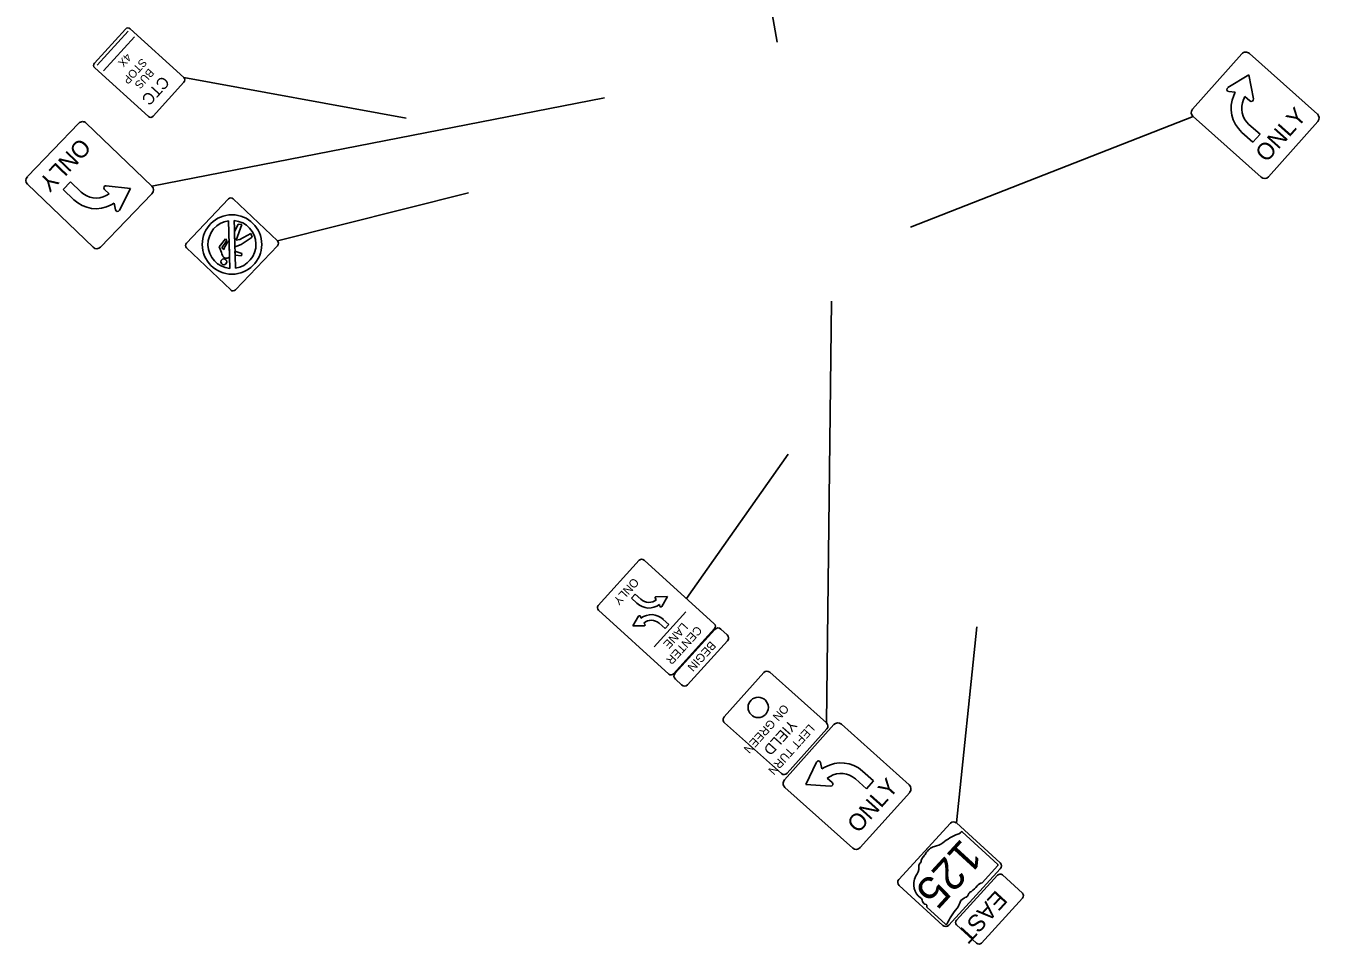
# Model space of a CAD drawing. Extents: x 1472333 to 1475205, y 385587 to 386650.
# Drawn here: x 1472409.3 to 1472790.9, y 386057.3 to 386328.4 of the extents above; entities that cross this region are included whole.
import ezdxf

# ---------------------------------------------------------------- set-up
doc = ezdxf.new("R2010")
doc.units = 0
doc.layers.add('RW_X_CL', color=7, linetype='Continuous')

msp = doc.modelspace()

# ---------------------------------------------------------------- linework, layer by layer
at = {"layer": 'RW_X_CL'}
for p, q in [((1472604.42, 386470.61), (1472631.01, 386323.53)), ((1472430.28, 386316.74), (1472439.42, 386326.82)), ((1472432.13, 386315.06), (1472441.27, 386325.14)), ((1472455.86, 386313.12), (1472521.45, 386301.15)), ((1472764, 386310.12), (1472770.19, 386313.94)), ((1472770.19, 386313.94), (1472771.52, 386306.79)), ((1472446.43, 386281.04), (1472580.06, 386307.15)), ((1472766.18, 386308.74), (1472764.26, 386308.96)), ((1472765.78, 386307.84), (1472766.18, 386308.74)), ((1472769.04, 386307.48), (1472768.64, 386306.57)), ((1472770.49, 386306.21), (1472769.04, 386307.48)), ((1472753.71, 386301.56), (1472670.31, 386268.98)), ((1472771.41, 386294.02), (1472768.14, 386296.93)), ((1472770.22, 386299.26), (1472773.49, 386296.35)), ((1472773.49, 386296.35), (1472771.41, 386294.02)), ((1472422.39, 386282.33), (1472420.22, 386280.08)), ((1472425.54, 386279.3), (1472422.39, 386282.33)), ((1472440.18, 386280.4), (1472432.95, 386281.17)), ((1472420.22, 386280.08), (1472423.38, 386277.04)), ((1472432.45, 386280.1), (1472433.83, 386278.75)), ((1472433.83, 386278.75), (1472432.96, 386278.28)), ((1472436.85, 386273.93), (1472440.18, 386280.4)), ((1472483.5, 386264.88), (1472539.84, 386279.08)), ((1472434.44, 386275.53), (1472435.31, 386276)), ((1472435.31, 386276), (1472435.68, 386274.1)), ((1472469.41, 386256.78), (1472469.08, 386270.86)), ((1472471.87, 386269.86), (1472470.83, 386267.61)), ((1472471.87, 386269.86), (1472470.83, 386267.61)), ((1472471.29, 386265.11), (1472472.98, 386269.73)), ((1472471.29, 386265.11), (1472472.98, 386269.73)), ((1472472.98, 386269.73), (1472471.87, 386269.86)), ((1472472.98, 386269.73), (1472471.87, 386269.86)), ((1472468.18, 386265.46), (1472466.28, 386263.14)), ((1472468.18, 386265.46), (1472466.28, 386263.14)), ((1472468.61, 386264.98), (1472468.18, 386265.46)), ((1472468.61, 386264.98), (1472468.18, 386265.46)), ((1472470.83, 386267.61), (1472470.94, 386263.24)), ((1472472.43, 386265.27), (1472471.29, 386265.11)), ((1472472.43, 386265.27), (1472471.29, 386265.11)), ((1472475.62, 386267.1), (1472472.43, 386265.27)), ((1472475.62, 386267.1), (1472472.43, 386265.27)), ((1472472.81, 386263.86), (1472476.01, 386266.02)), ((1472472.81, 386263.86), (1472476.01, 386266.02)), ((1472476.01, 386266.02), (1472475.62, 386267.1)), ((1472476.01, 386266.02), (1472475.62, 386267.1)), ((1472466.28, 386263.14), (1472466.3, 386263.13)), ((1472466.28, 386263.14), (1472466.3, 386263.13)), ((1472467.12, 386262.89), (1472468.61, 386264.98)), ((1472467.12, 386262.89), (1472468.61, 386264.98)), ((1472467.63, 386262.37), (1472467.12, 386262.89)), ((1472467.63, 386262.37), (1472467.12, 386262.89)), ((1472469.32, 386260.24), (1472469.21, 386264.79)), ((1472470.94, 386263.16), (1472471.48, 386263.34)), ((1472470.94, 386263.16), (1472471.48, 386263.34)), ((1472470.94, 386263.24), (1472470.94, 386263.16)), ((1472473.02, 386261.17), (1472470.97, 386261.86)), ((1472473.02, 386261.17), (1472470.97, 386261.86)), ((1472470.97, 386261.86), (1472470.98, 386261.63)), ((1472471.48, 386263.34), (1472472.81, 386263.86)), ((1472471.48, 386263.34), (1472472.81, 386263.86)), ((1472469.33, 386260.09), (1472469.32, 386260.24)), ((1472471, 386260.69), (1472472.91, 386260.47)), ((1472471, 386260.69), (1472472.91, 386260.47)), ((1472472.91, 386260.47), (1472473.02, 386261.17)), ((1472472.91, 386260.47), (1472473.02, 386261.17)), ((1472645.55, 386122.6), (1472647.04, 386247.1)), ((1472604.19, 386159.35), (1472634.2, 386201.93)), ((1472589.11, 386160.64), (1472587.99, 386159.41)), ((1472587.99, 386159.41), (1472589.59, 386157.96)), ((1472590.76, 386159.16), (1472589.11, 386160.64)), ((1472595, 386159.38), (1472595.36, 386159.05)), ((1472598.64, 386159.89), (1472595.29, 386159.88)), ((1472596.94, 386157.01), (1472598.64, 386159.89)), ((1472604.06, 386155.42), (1472594.65, 386145.04)), ((1472596.25, 386157.62), (1472596.38, 386157.01)), ((1472588.34, 386151.24), (1472590.02, 386154.1)), ((1472591.68, 386151.24), (1472588.34, 386151.24)), ((1472590.62, 386154.02), (1472590.76, 386153.53)), ((1472591.61, 386152.06), (1472591.97, 386151.74)), ((1472597.88, 386150.46), (1472596.12, 386152.05)), ((1472597.38, 386153.16), (1472599, 386151.69)), ((1472599, 386151.69), (1472597.88, 386150.46)), ((1472683.86, 386093.11), (1472689.89, 386150.97)), ((1472642.59, 386111.04), (1472639.49, 386104.46)), ((1472644.2, 386109.03), (1472643.76, 386110.92)), ((1472645.05, 386109.53), (1472644.2, 386109.03)), ((1472645.78, 386106.34), (1472646.63, 386106.84)), ((1472647.21, 386105.04), (1472645.78, 386106.34)), ((1472654.08, 386106.09), (1472657.34, 386103.17)), ((1472659.42, 386105.5), (1472656.16, 386108.42)), ((1472657.34, 386103.17), (1472659.42, 386105.5)), ((1472639.49, 386104.46), (1472646.74, 386103.95)), ((1472696.07, 386080.86), (1472685.58, 386090.48)), ((1472691.46, 386075.47), (1472696.1, 386080.53)), ((1472683.88, 386064.41), (1472696.04, 386077.68)), ((1472697.46, 386077.74), (1472703.35, 386072.34)), ((1472703.42, 386070.93), (1472691.26, 386057.65)), ((1472675.19, 386068.21), (1472680.68, 386063.18)), ((1472675.19, 386068.21), (1472675.19, 386068.21)), ((1472689.84, 386057.59), (1472683.94, 386063))]:
    msp.add_line(p, q, dxfattribs=at)
for points in [[(1472429.51, 386317.34), (1472438.65, 386327.41)], [(1472440.02, 386327.48), (1472455.86, 386313.12)], [(1472753.59, 386303.76), (1472768.14, 386320.09)], [(1472770.34, 386320.22), (1472790.41, 386302.34)], [(1472445.41, 386301.61), (1472429.58, 386315.97)], [(1472455.92, 386311.75), (1472446.78, 386301.67)], [(1472424.85, 386299.62), (1472409.69, 386283.85)], [(1472446.43, 386281.04), (1472427.06, 386299.66)], [(1472773.78, 386283.68), (1472753.71, 386301.56)], [(1472790.54, 386300.14), (1472775.98, 386283.8)], [(1472409.73, 386281.64), (1472429.11, 386263.01)], [(1472431.32, 386263.06), (1472446.47, 386278.83)], [(1472469.06, 386277.26), (1472456.64, 386264.23)], [(1472483.5, 386264.88), (1472470.47, 386277.3)], [(1472470.98, 386261.63), (1472470.94, 386263.24), (1472470.8, 386268.48), (1472470.74, 386270.9)], [(1472456.67, 386262.82), (1472469.7, 386250.4)], [(1472471.09, 386256.82), (1472471, 386260.65), (1472470.97, 386261.63), (1472470.98, 386261.63)], [(1472470.98, 386261.63), (1472471, 386260.69), (1472471, 386260.69)], [(1472471.12, 386250.43), (1472483.54, 386263.46)], [(1472469.32, 386260.24), (1472469.32, 386260.24)], [(1472590.28, 386170.61), (1472578.19, 386157.28)], [(1472612.43, 386151.87), (1472591.69, 386170.68)], [(1472578.26, 386155.86), (1472599, 386137.05)], [(1472600.41, 386137.12), (1472612.5, 386150.46)], [(1472600.85, 386137.27), (1472612.61, 386150.24)], [(1472616.31, 386146.88), (1472604.55, 386133.91)], [(1472614.37, 386150.32), (1472616.23, 386148.64)], [(1472602.79, 386133.83), (1472600.94, 386135.51)], [(1472615.35, 386124.45), (1472627.01, 386137.5)], [(1472628.78, 386137.59), (1472645.55, 386122.6)], [(1472632.22, 386107.69), (1472615.45, 386122.68)], [(1472647.72, 386122.11), (1472633.14, 386105.8)], [(1472645.65, 386120.83), (1472633.98, 386107.79)], [(1472669.96, 386104.32), (1472649.93, 386122.24)], [(1472633.27, 386103.6), (1472653.3, 386085.69)], [(1472655.51, 386085.81), (1472670.09, 386102.12)], [(1472666.89, 386076.45), (1472682.09, 386093.04)], [(1472683.86, 386093.11), (1472696.76, 386081.29)], [(1472696.84, 386079.52), (1472681.64, 386062.94)], [(1472679.87, 386062.86), (1472666.97, 386074.68)]]:
    msp.add_lwpolyline(points, dxfattribs=at)
for centre, radius in [((1472470.08, 386263.84), 8.77), ((1472467.66, 386258.72), 0.864), ((1472625.39, 386127.21), 3)]:
    msp.add_circle(centre, radius, dxfattribs=at)
for centre, radius, start, end in [((1472439.37, 386326.76), 0.972, 47.7891, 137.7891), ((1472769.3, 386319.06), 1.56, 48.3, 138.3), ((1472430.23, 386316.69), 0.972, 137.7891, 227.7891), ((1472455.2, 386312.4), 0.972, 317.7891, 47.7891), ((1472764.33, 386309.58), 0.625, 121.7347, 263.5064), ((1472774.45, 386304.01), 9.48, 156.1575, 228.3), ((1472754.75, 386302.72), 1.56, 138.3, 228.3), ((1472774.45, 386304.01), 6.35, 156.1613, 228.3), ((1472770.91, 386306.68), 0.625, 228.774, 10.5457), ((1472425.97, 386298.53), 1.56, 46.1321, 136.1321), ((1472446.06, 386302.32), 0.972, 227.7891, 317.7891), ((1472789.37, 386301.18), 1.56, 318.3, 48.3), ((1472410.81, 386282.76), 1.56, 136.1321, 226.1321), ((1472432.88, 386280.55), 0.625, 83.8864, 225.6581), ((1472445.35, 386279.91), 1.56, 316.1321, 46.1321), ((1472774.82, 386284.84), 1.56, 228.3, 318.3), ((1472429.95, 386283.88), 9.48, 226.1321, 298.2746), ((1472429.95, 386283.88), 6.35, 226.1321, 298.2708), ((1472469.78, 386276.57), 1, 46.3767, 136.3767), ((1472436.29, 386274.22), 0.625, 190.9257, 332.6974), ((1472470.08, 386263.84), 7.09, 98.1958, 264.5481), ((1472470.08, 386263.84), 7.09, 278.2247, 84.6247), ((1472470.08, 386263.84), 7.09, 278.2247, 84.6247), ((1472430.19, 386264.14), 1.56, 226.1321, 316.1321), ((1472457.36, 386263.54), 1, 136.3767, 226.3767), ((1472482.81, 386264.15), 1, 316.3767, 46.3767), ((1472470.39, 386251.12), 1, 226.3767, 316.3767), ((1472591.02, 386169.94), 1, 47.8, 137.8), ((1472593.12, 386161.6), 3.4, 225.9889, 311.4204), ((1472595.29, 386159.54), 0.334, 89.9541, 209.8), ((1472578.93, 386156.6), 1, 137.8, 227.8), ((1472593.12, 386161.6), 5.07, 225.8828, 308.2422), ((1472593.86, 386149.52), 5.07, 45.8828, 127.6482), ((1472596.66, 386157.19), 0.334, 213.4089, 327.7961), ((1472590.3, 386153.93), 0.334, 15.76, 147.7961), ((1472593.86, 386149.52), 3.4, 48.2572, 131.5022), ((1472591.68, 386151.57), 0.334, 269.9541, 29.8), ((1472611.76, 386151.13), 1, 317.8, 47.8), ((1472613.53, 386149.4), 1.25, 47.7922, 137.7922), ((1472615.39, 386147.72), 1.25, 317.7922, 47.7922), ((1472599.67, 386137.8), 1, 227.8, 317.8), ((1472601.78, 386136.43), 1.25, 137.7922, 227.7922), ((1472627.94, 386136.66), 1.25, 48.2, 138.2), ((1472603.63, 386134.75), 1.25, 227.7922, 317.7922), ((1472616.28, 386123.62), 1.25, 138.2, 228.2), ((1472644.72, 386121.67), 1.25, 318.2, 48.2), ((1472648.89, 386121.07), 1.56, 48.2, 138.2), ((1472643.15, 386110.78), 0.625, 12.9936, 154.7653), ((1472649.84, 386101.35), 9.48, 48.2, 120.3425), ((1472633.05, 386108.62), 1.25, 228.2, 318.2), ((1472634.31, 386104.76), 1.56, 138.2, 228.2), ((1472649.84, 386101.35), 6.35, 48.2, 120.3387), ((1472646.79, 386104.57), 0.625, 265.9543, 47.726), ((1472668.92, 386103.16), 1.56, 318.2, 48.2), ((1472683.01, 386092.19), 1.25, 47.5, 137.5), ((1472654.34, 386086.85), 1.56, 228.2, 318.2), ((1472695.92, 386080.37), 1.25, 317.5, 47.5), ((1472667.81, 386075.6), 1.25, 137.5, 227.5), ((1472696.78, 386077.01), 1, 47.5, 137.5), ((1472702.68, 386071.6), 1, 317.5, 47.5), ((1472680.72, 386063.78), 1.25, 227.5, 317.5), ((1472684.62, 386063.74), 1, 137.5, 227.5), ((1472690.52, 386058.33), 1, 227.5, 317.5)]:
    msp.add_arc(centre, radius, start, end, dxfattribs=at)
for centre, major_axis, start_param, end_param in [((1472687.47, 386074.83), (-12.13, -13.23), 4.195997, 4.488961), ((1472684.47, 386090.49), (-0.509, -0.556), 0.519207, 1.627899), ((1472686.42, 386089.29), (-1.41, -1.54), 4.665946, 4.897461), ((1472685.37, 386090.3), (-0.185, -0.202), 3.00124, 4.508301), ((1472677.5, 386082.99), (-2.41, -2.63), 4.026481, 4.996735), ((1472677.55, 386091.18), (-3.79, -4.14), 0.823519, 1.323587), ((1472675.15, 386082), (-1.28, -1.4), 4.691044, 5.507374), ((1472672.49, 386084.79), (-1.98, -2.16), 1.495662, 1.94098), ((1472669.73, 386079.09), (-2.3, -2.51), 1.647645, 2.488434), ((1472674.57, 386080.51), (-1.36, -1.48), 4.937069, 5.64225), ((1472672.97, 386081.66), (-0.361, -0.394), 1.147584, 2.315152), ((1472695.91, 386080.65), (-0.183, -0.2), 1.712693, 3.28349), ((1472676.89, 386076.08), (-4.2, -4.58), 5.101752, 6.440018), ((1472683.87, 386079.02), (-6.39, -6.97), 1.404758, 1.657858), ((1472691.57, 386073.15), (-1.78, -1.94), 4.042523, 4.731795), ((1472672.26, 386069.63), (-1.19, -1.3), 2.387724, 3.262537), ((1472686.53, 386069.39), (-1.28, -1.4), 4.081561, 5.145723), ((1472686.24, 386072.42), (-1.07, -1.16), 0.950623, 2.079405), ((1472688.21, 386072.13), (-0.513, -0.56), 3.836095, 5.185415), ((1472675.87, 386071.15), (-1.64, -1.79), 5.934695, 6.695948), ((1472674.83, 386068.62), (-0.273, -0.298), 1.883978, 3.671073), ((1472675.36, 386068.44), (-0.189, -0.206), 5.05454, 6.418171), ((1472700.36, 386056.47), (-16.79, -18.32), 4.814394, 5.042369), ((1472680.71, 386070.17), (-3.38, -3.69), 1.699011, 2.107814), ((1472680.88, 386063.35), (-0.176, -0.192), 6.141152, 7.989035)]:
    msp.add_ellipse(centre, major_axis=major_axis, ratio=0.8, start_param=start_param, end_param=end_param, dxfattribs=at)
for points in [[(1472466.3, 386263.13), (1472466.67, 386262.24), (1472467.24, 386260.82), (1472467.44, 386260.3), (1472467.54, 386260.16), (1472467.67, 386260.04), (1472467.96, 386259.77), (1472468.65, 386259.76), (1472469.06, 386259.97), (1472469.33, 386260.09)], [(1472466.3, 386263.13), (1472466.67, 386262.24), (1472467.24, 386260.82), (1472467.44, 386260.3), (1472467.54, 386260.16), (1472467.67, 386260.04), (1472467.96, 386259.77), (1472468.65, 386259.76), (1472469.06, 386259.97), (1472469.33, 386260.09)], [(1472469.21, 386264.79), (1472469.14, 386264.77), (1472468.95, 386264.66), (1472468.66, 386264.31), (1472468.44, 386263.95), (1472468.08, 386263.29), (1472467.85, 386262.82), (1472467.63, 386262.37)], [(1472469.21, 386264.79), (1472469.14, 386264.77), (1472468.95, 386264.66), (1472468.66, 386264.31), (1472468.44, 386263.95), (1472468.08, 386263.29), (1472467.85, 386262.82), (1472467.63, 386262.37)]]:
    msp.add_open_spline(points, degree=3, dxfattribs=at)

# ---------------------------------------------------------------- texts
for s, height, rotation, p in [('4X', 2.38, 227.7891, (1472438.91, 386320.48)), ('STOP', 2.38, 227.7891, (1472443.47, 386318.95)), ('BUS', 2.38, 227.7891, (1472445.57, 386315.96)), ('CTC', 3.4, 227.7891, (1472449.46, 386313.8)), ('ONLY', 5, 48.3, (1472775.38, 386287.82)), ('ONLY', 5, 226.1321, (1472425.3, 386295.58)), ('ONLY', 2.5, 227.8, (1472588.58, 386165.63)), ('LANE', 2.5, 227.8, (1472603.03, 386152.42)), ('CENTER', 2.5, 227.8, (1472607.23, 386151.46)), ('BEGIN', 2.5, 227.7922, (1472611.31, 386146.94)), ('ON GREEN', 2.503, 228.2, (1472632.82, 386128.34)), ('YIELD', 3.128, 228.2, (1472634.8, 386123.84)), ('LEFT TURN', 2.503, 228.2, (1472640.42, 386122.45)), ('ONLY', 5, 48.2, (1472654.91, 386089.83)), ('125', 9.375, 227.5, (1472685.4, 386088.8)), ('EAST', 5, 227.5, (1472695.62, 386073.51))]:
    msp.add_text(s, height=height, rotation=rotation, dxfattribs=at).set_placement(p)

doc.saveas('drawing.dxf')
